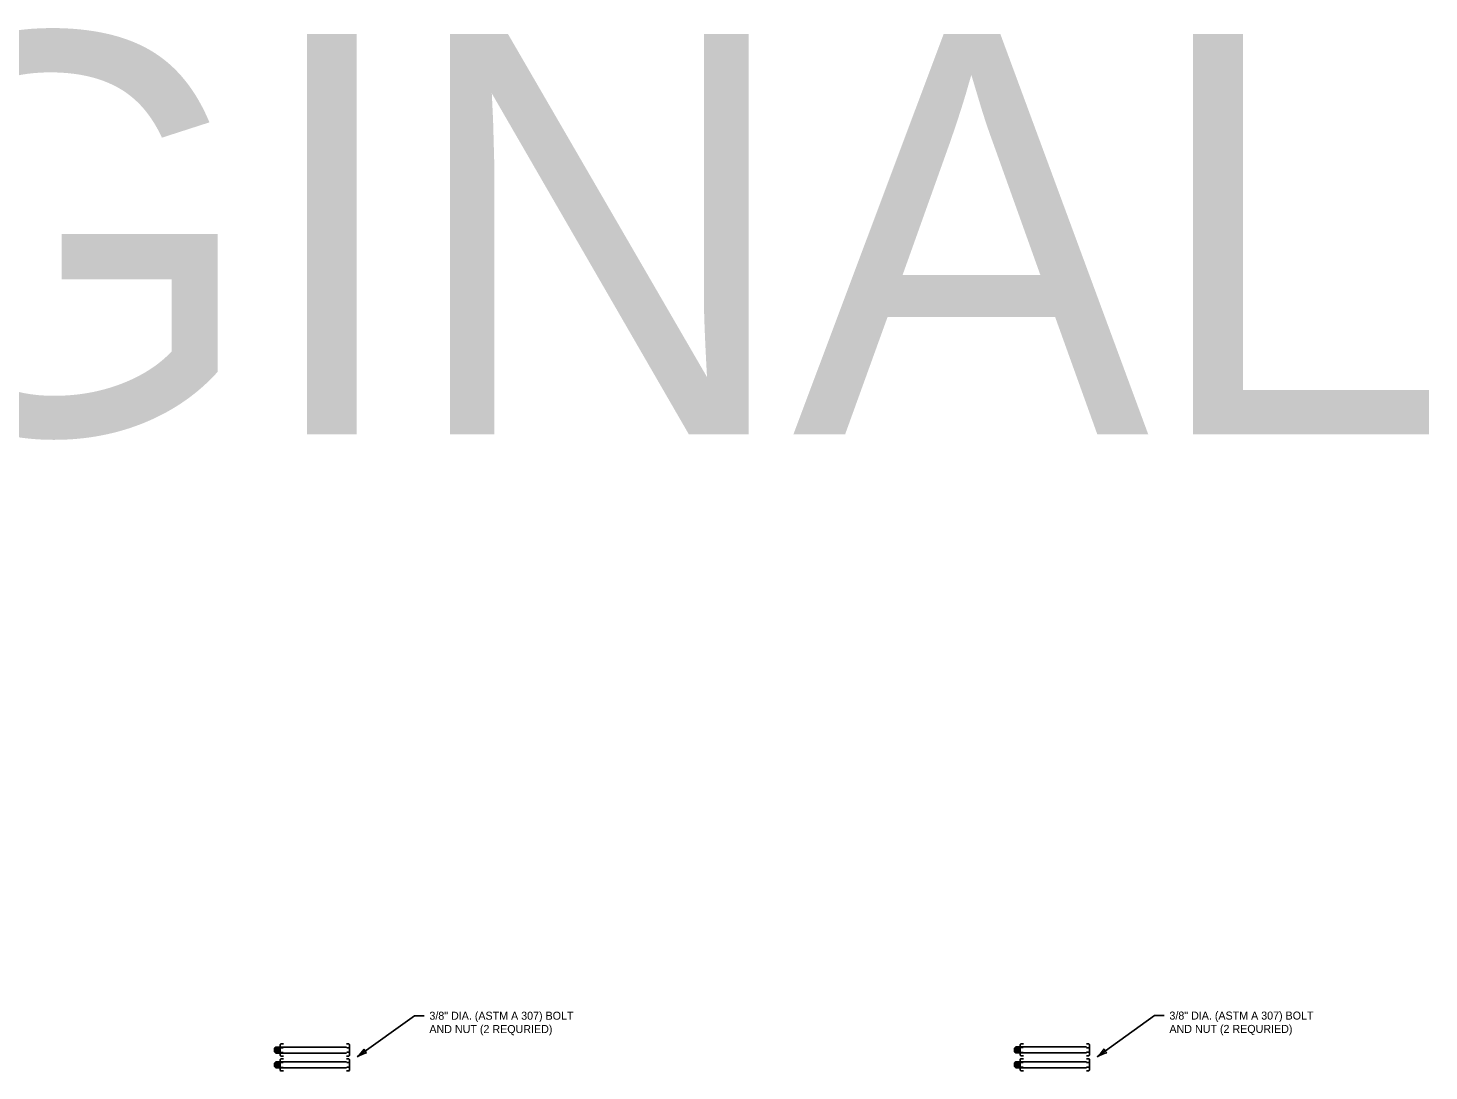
# Model space of a CAD drawing. Extents: x 49940 to 50043, y 49986 to 50011.
# Drawn here: x 49966.93 to 49977.44, y 49996.11 to 50003.93 of the extents above; entities that cross this region are included whole.
import ezdxf

# ---------------------------------------------------------------- set-up
doc = ezdxf.new("R2010")
doc.units = 0
for name, color, linetype in [('Level 1', 7, 'Continuous'), ('Level 2', 7, 'Continuous'), ('Level 3', 7, 'Continuous'), ('Level 4', 7, 'Continuous')]:
    doc.layers.add(name, color=color, linetype=linetype)

msp = doc.modelspace()

# ---------------------------------------------------------------- linework, layer by layer
at = {"layer": 'Level 1'}
for p, q in [((49968.778, 49996.282), (49968.787, 49996.291)), ((49968.778, 49996.255), (49968.778, 49996.282)), ((49968.778, 49996.255), (49968.787, 49996.246)), ((49968.783, 49996.255), (49968.783, 49996.285)), ((49968.821, 49996.291), (49968.787, 49996.291)), ((49968.787, 49996.246), (49968.787, 49996.291)), ((49968.792, 49996.255), (49968.792, 49996.285)), ((49968.796, 49996.246), (49968.796, 49996.291)), ((49968.801, 49996.255), (49968.801, 49996.285)), ((49968.806, 49996.246), (49968.806, 49996.291)), ((49968.81, 49996.255), (49968.81, 49996.285)), ((49968.815, 49996.246), (49968.815, 49996.291)), ((49968.821, 49996.31), (49968.825, 49996.314)), ((49968.821, 49996.228), (49968.821, 49996.31)), ((49968.821, 49996.286), (49968.843, 49996.286)), ((49968.821, 49996.25), (49968.843, 49996.25)), ((49968.844, 49996.314), (49968.825, 49996.314)), ((49969.335, 49996.314), (49969.318, 49996.314)), ((49969.339, 49996.285), (49969.319, 49996.285)), ((49969.339, 49996.252), (49969.319, 49996.252)), ((49969.339, 49996.31), (49969.335, 49996.314)), ((49969.339, 49996.228), (49969.339, 49996.31)), ((49974.328, 49996.283), (49974.337, 49996.292)), ((49974.328, 49996.256), (49974.328, 49996.283)), ((49974.328, 49996.256), (49974.337, 49996.247)), ((49974.332, 49996.256), (49974.332, 49996.286)), ((49974.37, 49996.292), (49974.337, 49996.292)), ((49974.337, 49996.247), (49974.337, 49996.292)), ((49974.341, 49996.256), (49974.341, 49996.286)), ((49974.346, 49996.247), (49974.346, 49996.292)), ((49974.35, 49996.256), (49974.35, 49996.286)), ((49974.355, 49996.247), (49974.355, 49996.292)), ((49974.36, 49996.256), (49974.36, 49996.286)), ((49974.364, 49996.247), (49974.364, 49996.292)), ((49974.37, 49996.311), (49974.375, 49996.315)), ((49974.37, 49996.229), (49974.37, 49996.311)), ((49974.37, 49996.287), (49974.392, 49996.287)), ((49974.37, 49996.251), (49974.392, 49996.251)), ((49974.394, 49996.315), (49974.375, 49996.315)), ((49974.884, 49996.315), (49974.868, 49996.315)), ((49974.889, 49996.286), (49974.868, 49996.286)), ((49974.889, 49996.253), (49974.868, 49996.253)), ((49974.889, 49996.311), (49974.884, 49996.315)), ((49974.889, 49996.229), (49974.889, 49996.311)), ((49968.778, 49996.171), (49968.787, 49996.18)), ((49968.778, 49996.144), (49968.778, 49996.171)), ((49968.783, 49996.144), (49968.783, 49996.174)), ((49968.821, 49996.246), (49968.787, 49996.246)), ((49968.821, 49996.18), (49968.787, 49996.18)), ((49968.787, 49996.134), (49968.787, 49996.18)), ((49968.792, 49996.144), (49968.792, 49996.174)), ((49968.796, 49996.134), (49968.796, 49996.18)), ((49968.801, 49996.144), (49968.801, 49996.174)), ((49968.806, 49996.134), (49968.806, 49996.18)), ((49968.81, 49996.144), (49968.81, 49996.174)), ((49968.815, 49996.134), (49968.815, 49996.18)), ((49968.821, 49996.228), (49968.825, 49996.223)), ((49968.821, 49996.198), (49968.825, 49996.203)), ((49968.821, 49996.116), (49968.821, 49996.198)), ((49968.821, 49996.175), (49968.843, 49996.175)), ((49968.844, 49996.223), (49968.825, 49996.223)), ((49968.844, 49996.203), (49968.825, 49996.203)), ((49969.335, 49996.223), (49969.318, 49996.223)), ((49969.335, 49996.203), (49969.318, 49996.203)), ((49969.339, 49996.174), (49969.319, 49996.174)), ((49969.335, 49996.223), (49969.339, 49996.228)), ((49969.339, 49996.198), (49969.335, 49996.203)), ((49969.339, 49996.116), (49969.339, 49996.198)), ((49974.328, 49996.172), (49974.337, 49996.181)), ((49974.328, 49996.144), (49974.328, 49996.172)), ((49974.332, 49996.145), (49974.332, 49996.174)), ((49974.37, 49996.247), (49974.337, 49996.247)), ((49974.37, 49996.181), (49974.337, 49996.181)), ((49974.337, 49996.135), (49974.337, 49996.181)), ((49974.341, 49996.145), (49974.341, 49996.174)), ((49974.346, 49996.135), (49974.346, 49996.181)), ((49974.35, 49996.145), (49974.35, 49996.174)), ((49974.355, 49996.135), (49974.355, 49996.181)), ((49974.36, 49996.145), (49974.36, 49996.174)), ((49974.364, 49996.135), (49974.364, 49996.181)), ((49974.37, 49996.229), (49974.375, 49996.224)), ((49974.37, 49996.199), (49974.375, 49996.203)), ((49974.37, 49996.117), (49974.37, 49996.199)), ((49974.37, 49996.175), (49974.392, 49996.175)), ((49974.394, 49996.224), (49974.375, 49996.224)), ((49974.394, 49996.203), (49974.375, 49996.203)), ((49974.884, 49996.224), (49974.868, 49996.224)), ((49974.884, 49996.203), (49974.868, 49996.203)), ((49974.889, 49996.174), (49974.868, 49996.174)), ((49974.884, 49996.224), (49974.889, 49996.229)), ((49974.889, 49996.199), (49974.884, 49996.203)), ((49974.889, 49996.117), (49974.889, 49996.199)), ((49968.778, 49996.144), (49968.787, 49996.134)), ((49968.821, 49996.134), (49968.787, 49996.134)), ((49968.821, 49996.138), (49968.843, 49996.138)), ((49968.821, 49996.116), (49968.825, 49996.112)), ((49968.844, 49996.112), (49968.825, 49996.112)), ((49969.335, 49996.112), (49969.318, 49996.112)), ((49969.339, 49996.141), (49969.319, 49996.141)), ((49969.335, 49996.112), (49969.339, 49996.116)), ((49974.328, 49996.144), (49974.337, 49996.135)), ((49974.37, 49996.135), (49974.337, 49996.135)), ((49974.37, 49996.139), (49974.392, 49996.139)), ((49974.37, 49996.117), (49974.375, 49996.113)), ((49974.394, 49996.113), (49974.375, 49996.113)), ((49974.889, 49996.141), (49974.868, 49996.141)), ((49974.884, 49996.113), (49974.868, 49996.113)), ((49974.884, 49996.113), (49974.889, 49996.117))]:
    msp.add_line(p, q, dxfattribs=at)
at = {"layer": 'Level 3'}
for p, q in [((49969.827, 49996.526), (49969.397, 49996.217)), ((49969.899, 49996.526), (49969.827, 49996.526)), ((49975.377, 49996.527), (49974.947, 49996.218)), ((49975.449, 49996.527), (49975.377, 49996.527))]:
    msp.add_line(p, q, dxfattribs=at)
for centre, radius, start, end in [((49969.252, 49996.4), 0.233, 308.5027, 327.7526), ((49969.501, 49996.292), 0.0548, 197.8142, 233.5366), ((49974.802, 49996.401), 0.233, 308.5027, 327.7526), ((49975.051, 49996.293), 0.0548, 197.8142, 233.5366), ((49969.519, 49996.032), 0.222, 103.1314, 123.3149), ((49975.069, 49996.032), 0.222, 103.1314, 123.3149)]:
    msp.add_arc(centre, radius, start, end, dxfattribs=at)
at = {"layer": 'Level 4'}
for p, q in [((49969.318, 49996.291), (49968.821, 49996.291)), ((49974.868, 49996.292), (49974.37, 49996.292)), ((49969.318, 49996.246), (49968.821, 49996.246)), ((49969.318, 49996.18), (49968.821, 49996.18)), ((49974.868, 49996.247), (49974.37, 49996.247)), ((49974.868, 49996.181), (49974.37, 49996.181)), ((49969.318, 49996.134), (49968.821, 49996.134)), ((49974.868, 49996.135), (49974.37, 49996.135))]:
    msp.add_line(p, q, dxfattribs=at)

# ---------------------------------------------------------------- texts
at = {"layer": 'Level 2'}
for s, p in [('3/8" DIA. (ASTM A 307) BOLT ', (49969.939, 49996.496)), ('AND NUT (2 REQURIED)', (49975.489, 49996.397)), ('3/8" DIA. (ASTM A 307) BOLT ', (49975.489, 49996.497)), ('AND NUT (2 REQURIED)', (49969.939, 49996.396))]:
    msp.add_text(s, height=0.06, dxfattribs=at).set_placement(p)
at = {"layer": 'Level 3'}
msp.add_text('ENGLISH ORIGINAL', height=3, dxfattribs=at).set_placement((49939.671, 50000.886))

doc.saveas('drawing.dxf')
